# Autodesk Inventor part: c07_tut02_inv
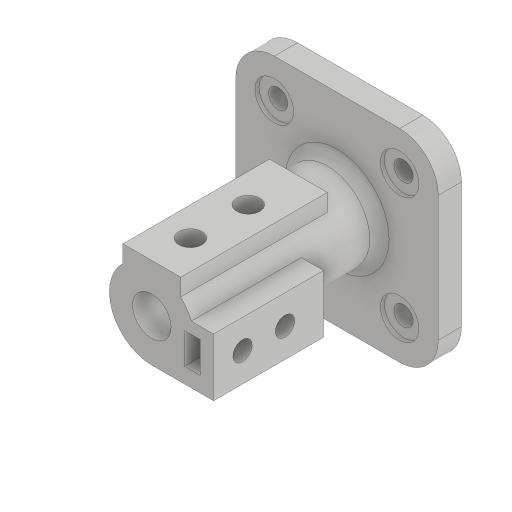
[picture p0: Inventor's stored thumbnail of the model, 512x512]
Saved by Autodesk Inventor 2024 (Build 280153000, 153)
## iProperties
Created: 2017-04
Part Number: c07_tut02_inv
Material: Generic
Document SubType Name: Modeling
Designer: CADCIM 00
Density: 1 g/cm^3
Appearance: Default
Author: CADCIM 00
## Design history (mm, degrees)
sketch "Sketch1"
  geometry: L1 (-32.5, -52.5)-(32.5, -52.5); L2 (52.5, -32.5)-(52.5, 32.5); L3 (32.5, 52.5)-(-32.5, 52.5); L4 (-52.5, 32.5)-(-52.5, -32.5); L5 (-52.5, -52.5)-(52.5, 52.5); L6 (52.5, -52.5)-(-52.5, 52.5); A1 r 20 centre (32.5, 32.5) between (52.5, 32.5) and (32.5, 52.5); A2 r 20 centre (-32.5, 32.5) between (-32.5, 52.5) and (-52.5, 32.5); A3 r 20 centre (-32.5, -32.5) between (-52.5, -32.5) and (-32.5, -52.5); A4 r 20 centre (32.5, -32.5) between (32.5, -52.5) and (52.5, -32.5); 1 further point
  constraints: 12 end point, 8 point on circle, 8 point on line, 8 tangent, 4 centre point, 3 equal radius, 2 midpoint, 2 parallel, 2 perpendicular, 1 horizontal
  dimensions: "d0" = 105 distance of L5.end L6.end; "d1" = 20 radius of A1
extrude "Extrusion1" new body sketch "Sketch1" distance "d2" = 12; taper "d3" = 0 deg
sketch "Sketch10"
  geometry: A1 r 20 centre (32.5, 32.5) between (52.5, 32.5) and (32.5, 52.5) reference; 1 further point
  constraints: 1 coincident
hole "Hole1" sketch "Sketch10" diameter "d6" = 10; stored, may be unused: countersink angle "d10" = 90 deg, drill point angle "d12" = 118 deg; dims "d7" = 6, "d8" = 20, "d9" = 2, "d11" = 8
hole "Hole2" diameter "d15" = 10; stored, may be unused: countersink angle "d19" = 90 deg, drill point angle "d21" = 118 deg; dims "d13" = 10, "d14" = 10, "d16" = 6, "d17" = 20, "d18" = 2, "d20" = 8
hole "Hole3" diameter "d24" = 10; stored, may be unused: countersink angle "d28" = 90 deg, drill point angle "d30" = 118 deg; dims "d22" = 10, "d23" = 10, "d25" = 6, "d26" = 20, "d27" = 2, "d29" = 8
hole "Hole4" diameter "d33" = 10; stored, may be unused: countersink angle "d37" = 90 deg, drill point angle "d39" = 118 deg; dims "d31" = 10, "d32" = 10, "d34" = 6, "d35" = 20, "d36" = 2, "d38" = 8
sketch "Sketch2"
  geometry: C1 r 22 at (0, 0); 1 further point
  constraints: 1 centre point, 1 coincident
  dimensions: "d40" = 44 diameter of C1
extrude "Extrusion2" join sketch "Sketch2" distance "d41" = 96; taper "d42" = 0 deg
sketch "Sketch3"
  geometry: L1 (-15, 25)-(15, 25); L2 (15, 25)-(15, 16.093); L3 (-15, 16.093)-(-15, 25); L4 (0, 0)-(0, 59.776); A1 r 22 centre (0, 0) between (-15, 16.093) and (15, 16.093) reference; 1 further point
  constraints: 8 end point, 2 point on circle, 1 horizontal, 1 parallel, 1 perpendicular, 1 vertical, 1 other
  dimensions: "d43" = 30 distance between parallel lines of L2 L3; "d44" = 25 distance from line of L1 point (0, 0)
extrude "Extrusion3" join sketch "Sketch3" distance "d45" = 76; taper "d46" = 0 deg
sketch "Sketch4"
  geometry: L1 (32, 8)-(20.494, 8); L2 (32, -22)-(32, 8); L3 (0, 0)-(52.5, 0); L4 (52.5, -32.5)-(52.5, 32.5) reference; L5 (0, -22)-(32, -22); A1 r 22 centre (0, 0) between (-15, 16.093) and (15, 16.093) reference; 1 further point
  constraints: 8 end point, 3 horizontal, 2 point on circle, 1 midpoint, 1 tangent, 1 vertical
  dimensions: "d47" = 30 distance of L2.start L1.start; "d48" = 32 distance from line of point (0, 0) L2
extrude "Extrusion4" join sketch "Sketch4" distance "d49" = 57; taper "d50" = 0 deg
sketch "Sketch6"
  geometry: L1 (25, 2)-(17, 2); L2 (17, 2)-(17, -14); L3 (17, -14)-(25, -14); L4 (25, -14)-(25, 2); L5 (0, 0)-(52.778, 0)
  constraints: 10 end point, 2 horizontal, 2 parallel, 1 perpendicular
  dimensions: "d51" = 8 distance of L1.start L1.end; "d52" = 16 distance of L3.end L1.start; "d53" = 25 distance from line of L4 L5.start; "d72" = 2 distance between parallel lines of L1 L5
extrude "Extrusion5" cut sketch "Sketch6" distance "d54" = 50; taper "d55" = 0 deg
sketch "Sketch7"
  geometry: C1 r 10 at (0, 0); 1 further point
  constraints: 1 centre point, 1 coincident
  dimensions: "d56" = 20 diameter of C1
extrude "Extrusion6" cut sketch "Sketch7" stored distance "d57" = 57; taper "d58" = 0 deg
sketch "Sketch8"
  geometry: L1 (30, 0)-(0, 0) reference; L2 (0, 0)-(0, 76) reference; C1 r 6 at (15, 50); C2 r 6 at (15, 20); 1 further point
  constraints: 2 centre point, 1 equal radius, 1 vertical alignment
  dimensions: "d59" = 30 distance of C2.centre C1.centre; "d60" = 12 diameter of C1; "d61" = 20 distance from line of L1 C2.centre; "d62" = 15 distance from line of L2 C2.centre
extrude "Extrusion7" cut sketch "Sketch8" stored distance "d63" = 57; taper "d64" = 0 deg
sketch "Sketch9"
  geometry: L1 (0, 0)-(0, 57) reference; L2 (30, 0)-(0, 0) reference; C1 r 5 at (15, 15); C2 r 5 at (15, 37); 1 further point
  constraints: 2 centre point, 1 equal radius, 1 vertical alignment
  dimensions: "d65" = 10 diameter of C1; "d66" = 22 distance of C2.centre C1.centre; "d67" = 15 distance from line of L1 C1.centre; "d68" = 15 distance from line of L2 C1.centre
extrude "Extrusion8" cut sketch "Sketch9" stored distance "d69" = 57; taper "d70" = 0 deg
fillet "Fillet1" dims "d71" = 5
body "Solid1"
